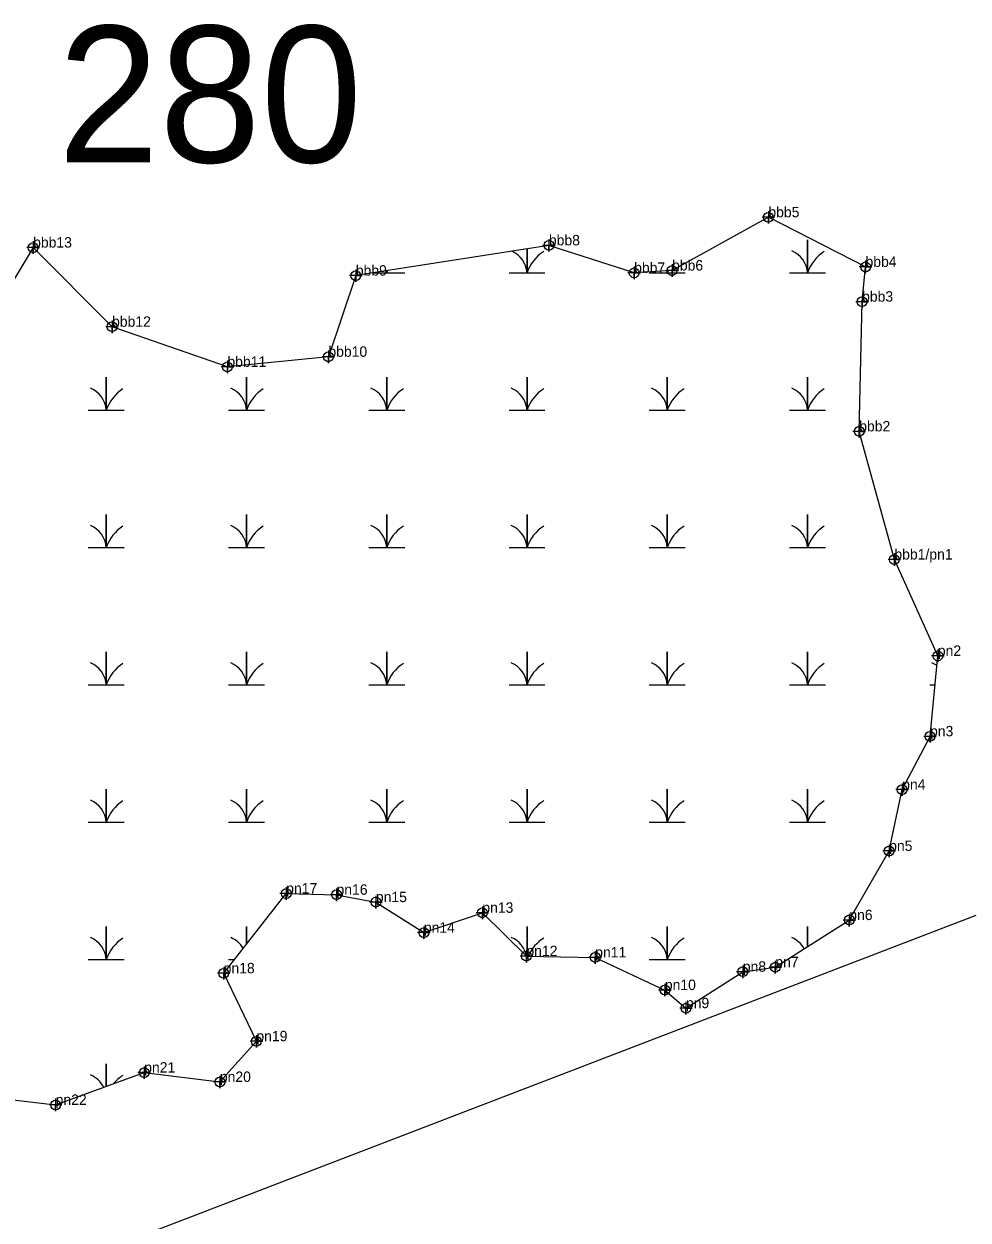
# Model space of a CAD drawing. Extents: x 2071991 to 2268989, y 436479 to 469629.
# Drawn here: x 2242081 to 2242534, y 439959 to 440532 of the extents above; entities that cross this region are included whole.
import ezdxf

# ---------------------------------------------------------------- set-up
doc = ezdxf.new("R2010")
doc.units = 0
for name, color, linetype in [('approx_PSA', 7, 'Continuous'), ('Default', 7, 'Continuous'), ('Exist Environmental Wetland Boundary', 7, 'Continuous'), ('Exist Environmental Wetland Boundary Cogo Comment', 7, 'Continuous'), ('Exist Environmental Wetland Boundary Cogo Point CELL', 7, 'Continuous'), ('Exist Hydro Swamp or Marsh', 7, 'Continuous')]:
    doc.layers.add(name, color=color, linetype=linetype)

msp = doc.modelspace()

# ---------------------------------------------------------------- linework, layer by layer
at = {"layer": 'approx_PSA'}
msp.add_line((2242537.57, 440104.72), (2241491, 439703.18), dxfattribs=at)
at = {"layer": 'Exist Environmental Wetland Boundary'}
msp.add_lwpolyline([(2242062.43, 440018.03), (2242096.69, 440014.03), (2242139.12, 440029.51), (2242175.36, 440025.04), (2242192.89, 440044.51), (2242177.2, 440077.07), (2242207.17, 440115.29), (2242231.28, 440114.71), (2242250.14, 440111.17), (2242273.12, 440096.55), (2242301.15, 440106.06), (2242322.27, 440085.32), (2242355.23, 440084.68), (2242388.6, 440069.06), (2242398.71, 440060.37), (2242425.95, 440077.83), (2242441.53, 440080.02), (2242476.97, 440102.58), (2242496.07, 440135.68), (2242502.31, 440165.05), (2242515.66, 440190.59), (2242519.41, 440229.14), (2242498.59, 440275.3), (2242481.72, 440336.67), (2242483.1, 440398.81), (2242484.75, 440415.48), (2242438.2, 440439.24), (2242392.06, 440413.73), (2242373.89, 440412.62), (2242333.04, 440425.78), (2242240.52, 440411.29), (2242227.38, 440372.41), (2242179, 440367.6), (2242123.71, 440386.79), (2242085.9, 440424.73), (2242061.66, 440384.54)], dxfattribs=at)
at = {"layer": 'Exist Environmental Wetland Boundary Cogo Point CELL'}
for points in [[(2242438.2, 440442.24), (2242438.2, 440436.24), (2242438.2, 440439.24), (2242441.2, 440439.24), (2242435.2, 440439.24)], [(2242333.04, 440428.78), (2242333.04, 440422.78), (2242333.04, 440425.78), (2242336.04, 440425.78), (2242330.04, 440425.78)], [(2242085.9, 440427.73), (2242085.9, 440421.73), (2242085.9, 440424.73), (2242088.9, 440424.73), (2242082.9, 440424.73)], [(2242392.06, 440416.73), (2242392.06, 440410.73), (2242392.06, 440413.73), (2242395.06, 440413.73), (2242389.06, 440413.73)], [(2242484.75, 440418.48), (2242484.75, 440412.48), (2242484.75, 440415.48), (2242487.75, 440415.48), (2242481.75, 440415.48)], [(2242240.52, 440414.29), (2242240.52, 440408.29), (2242240.52, 440411.29), (2242243.52, 440411.29), (2242237.52, 440411.29)], [(2242373.89, 440415.62), (2242373.89, 440409.62), (2242373.89, 440412.62), (2242376.89, 440412.62), (2242370.89, 440412.62)], [(2242483.1, 440401.81), (2242483.1, 440395.81), (2242483.1, 440398.81), (2242486.1, 440398.81), (2242480.1, 440398.81)], [(2242123.71, 440389.79), (2242123.71, 440383.79), (2242123.71, 440386.79), (2242126.71, 440386.79), (2242120.71, 440386.79)], [(2242179, 440370.6), (2242179, 440364.6), (2242179, 440367.6), (2242182, 440367.6), (2242176, 440367.6)], [(2242227.38, 440375.41), (2242227.38, 440369.41), (2242227.38, 440372.41), (2242230.38, 440372.41), (2242224.38, 440372.41)], [(2242481.72, 440339.67), (2242481.72, 440333.67), (2242481.72, 440336.67), (2242484.72, 440336.67), (2242478.72, 440336.67)], [(2242498.59, 440278.3), (2242498.59, 440272.3), (2242498.59, 440275.3), (2242501.59, 440275.3), (2242495.59, 440275.3)], [(2242519.41, 440232.14), (2242519.41, 440226.14), (2242519.41, 440229.14), (2242522.41, 440229.14), (2242516.41, 440229.14)], [(2242515.66, 440193.59), (2242515.66, 440187.59), (2242515.66, 440190.59), (2242518.66, 440190.59), (2242512.66, 440190.59)], [(2242502.31, 440168.05), (2242502.31, 440162.05), (2242502.31, 440165.05), (2242505.31, 440165.05), (2242499.31, 440165.05)], [(2242496.07, 440138.68), (2242496.07, 440132.68), (2242496.07, 440135.68), (2242499.07, 440135.68), (2242493.07, 440135.68)], [(2242207.17, 440118.29), (2242207.17, 440112.29), (2242207.17, 440115.29), (2242210.17, 440115.29), (2242204.17, 440115.29)], [(2242231.28, 440117.71), (2242231.28, 440111.71), (2242231.28, 440114.71), (2242234.28, 440114.71), (2242228.28, 440114.71)], [(2242250.14, 440114.17), (2242250.14, 440108.17), (2242250.14, 440111.17), (2242253.14, 440111.17), (2242247.14, 440111.17)], [(2242301.15, 440109.06), (2242301.15, 440103.06), (2242301.15, 440106.06), (2242304.15, 440106.06), (2242298.15, 440106.06)], [(2242476.97, 440105.58), (2242476.97, 440099.58), (2242476.97, 440102.58), (2242479.97, 440102.58), (2242473.97, 440102.58)], [(2242273.12, 440099.55), (2242273.12, 440093.55), (2242273.12, 440096.55), (2242276.12, 440096.55), (2242270.12, 440096.55)], [(2242322.27, 440088.32), (2242322.27, 440082.32), (2242322.27, 440085.32), (2242325.27, 440085.32), (2242319.27, 440085.32)], [(2242355.23, 440087.68), (2242355.23, 440081.68), (2242355.23, 440084.68), (2242358.23, 440084.68), (2242352.23, 440084.68)], [(2242177.2, 440080.07), (2242177.2, 440074.07), (2242177.2, 440077.07), (2242180.2, 440077.07), (2242174.2, 440077.07)], [(2242425.95, 440080.83), (2242425.95, 440074.83), (2242425.95, 440077.83), (2242428.95, 440077.83), (2242422.95, 440077.83)], [(2242441.53, 440083.02), (2242441.53, 440077.02), (2242441.53, 440080.02), (2242444.53, 440080.02), (2242438.53, 440080.02)], [(2242388.6, 440072.06), (2242388.6, 440066.06), (2242388.6, 440069.06), (2242391.6, 440069.06), (2242385.6, 440069.06)], [(2242398.71, 440063.37), (2242398.71, 440057.37), (2242398.71, 440060.37), (2242401.71, 440060.37), (2242395.71, 440060.37)], [(2242192.89, 440047.51), (2242192.89, 440041.51), (2242192.89, 440044.51), (2242195.89, 440044.51), (2242189.89, 440044.51)], [(2242139.12, 440032.51), (2242139.12, 440026.51), (2242139.12, 440029.51), (2242142.12, 440029.51), (2242136.12, 440029.51)], [(2242175.36, 440028.04), (2242175.36, 440022.04), (2242175.36, 440025.04), (2242178.36, 440025.04), (2242172.36, 440025.04)], [(2242096.69, 440017.03), (2242096.69, 440011.03), (2242096.69, 440014.03), (2242099.69, 440014.03), (2242093.69, 440014.03)]]:
    msp.add_lwpolyline(points, dxfattribs=at)
for centre in [(2242438.2, 440439.24), (2242333.04, 440425.78), (2242085.9, 440424.73), (2242484.75, 440415.48), (2242240.52, 440411.29), (2242373.89, 440412.62), (2242392.06, 440413.73), (2242483.1, 440398.81), (2242123.71, 440386.79), (2242227.38, 440372.41), (2242179, 440367.6), (2242481.72, 440336.67), (2242498.59, 440275.3), (2242519.41, 440229.14), (2242515.66, 440190.59), (2242502.31, 440165.05), (2242496.07, 440135.68), (2242207.17, 440115.29), (2242231.28, 440114.71), (2242250.14, 440111.17), (2242301.15, 440106.06), (2242476.97, 440102.58), (2242273.12, 440096.55), (2242322.27, 440085.32), (2242355.23, 440084.68), (2242177.2, 440077.07), (2242425.95, 440077.83), (2242441.53, 440080.02), (2242388.6, 440069.06), (2242398.71, 440060.37), (2242192.89, 440044.51), (2242139.12, 440029.51), (2242175.36, 440025.04), (2242096.69, 440014.03)]:
    msp.add_circle(centre, 2.34, dxfattribs=at)
at = {"layer": 'Exist Hydro Swamp or Marsh'}
for p, q in [((2242515.56, 440215.3), (2242518.06, 440215.3)), ((2242179.54, 440083.74), (2242182.43, 440083.74))]:
    msp.add_line(p, q, dxfattribs=at)
for points in [[(2242448.35, 440412.64), (2242456.96, 440412.64), (2242456.96, 440428.42), (2242456.96, 440412.64), (2242465.56, 440412.64)], [(2242313.95, 440412.64), (2242322.55, 440412.64), (2242322.55, 440424.13)], [(2242322.55, 440424.13), (2242322.55, 440412.64), (2242331.15, 440412.64)], [(2242249.11, 440412.64), (2242255.35, 440412.64), (2242255.35, 440413.61)], [(2242255.35, 440413.61), (2242255.35, 440412.64), (2242263.95, 440412.64)], [(2242381.15, 440412.64), (2242389.75, 440412.64), (2242389.75, 440413.58)], [(2242389.75, 440413.58), (2242389.75, 440412.64), (2242398.35, 440412.64)], [(2242112.34, 440346.86), (2242120.94, 440346.86), (2242120.94, 440362.64), (2242120.94, 440346.86), (2242129.54, 440346.86)], [(2242179.54, 440346.86), (2242188.14, 440346.86), (2242188.14, 440362.64), (2242188.14, 440346.86), (2242196.74, 440346.86)], [(2242246.74, 440346.86), (2242255.35, 440346.86), (2242255.35, 440362.64), (2242255.35, 440346.86), (2242263.95, 440346.86)], [(2242313.95, 440346.86), (2242322.55, 440346.86), (2242322.55, 440362.64), (2242322.55, 440346.86), (2242331.15, 440346.86)], [(2242381.15, 440346.86), (2242389.75, 440346.86), (2242389.75, 440362.64), (2242389.75, 440346.86), (2242398.35, 440346.86)], [(2242448.35, 440346.86), (2242456.96, 440346.86), (2242456.96, 440362.64), (2242456.96, 440346.86), (2242465.56, 440346.86)], [(2242112.34, 440281.08), (2242120.94, 440281.08), (2242120.94, 440296.86), (2242120.94, 440281.08), (2242129.54, 440281.08)], [(2242179.54, 440281.08), (2242188.14, 440281.08), (2242188.14, 440296.86), (2242188.14, 440281.08), (2242196.74, 440281.08)], [(2242246.74, 440281.08), (2242255.35, 440281.08), (2242255.35, 440296.86), (2242255.35, 440281.08), (2242263.95, 440281.08)], [(2242313.95, 440281.08), (2242322.55, 440281.08), (2242322.55, 440296.86), (2242322.55, 440281.08), (2242331.15, 440281.08)], [(2242381.15, 440281.08), (2242389.75, 440281.08), (2242389.75, 440296.86), (2242389.75, 440281.08), (2242398.35, 440281.08)], [(2242448.35, 440281.08), (2242456.96, 440281.08), (2242456.96, 440296.86), (2242456.96, 440281.08), (2242465.56, 440281.08)], [(2242112.34, 440215.3), (2242120.94, 440215.3), (2242120.94, 440231.08), (2242120.94, 440215.3), (2242129.54, 440215.3)], [(2242179.54, 440215.3), (2242188.14, 440215.3), (2242188.14, 440231.08), (2242188.14, 440215.3), (2242196.74, 440215.3)], [(2242246.74, 440215.3), (2242255.35, 440215.3), (2242255.35, 440231.08), (2242255.35, 440215.3), (2242263.95, 440215.3)], [(2242313.95, 440215.3), (2242322.55, 440215.3), (2242322.55, 440231.08), (2242322.55, 440215.3), (2242331.15, 440215.3)], [(2242381.15, 440215.3), (2242389.75, 440215.3), (2242389.75, 440231.08), (2242389.75, 440215.3), (2242398.35, 440215.3)], [(2242448.35, 440215.3), (2242456.96, 440215.3), (2242456.96, 440231.08), (2242456.96, 440215.3), (2242465.56, 440215.3)], [(2242112.34, 440149.52), (2242120.94, 440149.52), (2242120.94, 440165.3), (2242120.94, 440149.52), (2242129.54, 440149.52)], [(2242179.54, 440149.52), (2242188.14, 440149.52), (2242188.14, 440165.3), (2242188.14, 440149.52), (2242196.74, 440149.52)], [(2242246.74, 440149.52), (2242255.35, 440149.52), (2242255.35, 440165.3), (2242255.35, 440149.52), (2242263.95, 440149.52)], [(2242313.95, 440149.52), (2242322.55, 440149.52), (2242322.55, 440165.3), (2242322.55, 440149.52), (2242331.15, 440149.52)], [(2242381.15, 440149.52), (2242389.75, 440149.52), (2242389.75, 440165.3), (2242389.75, 440149.52), (2242398.35, 440149.52)], [(2242448.35, 440149.52), (2242456.96, 440149.52), (2242456.96, 440165.3), (2242456.96, 440149.52), (2242465.56, 440149.52)], [(2242112.34, 440083.74), (2242120.94, 440083.74), (2242120.94, 440099.52), (2242120.94, 440083.74), (2242129.54, 440083.74)], [(2242188.14, 440091.03), (2242188.14, 440099.52), (2242188.14, 440091.03)], [(2242322.55, 440085.32), (2242322.55, 440099.52), (2242322.55, 440085.32)], [(2242381.15, 440083.74), (2242389.75, 440083.74), (2242389.75, 440099.52), (2242389.75, 440083.74), (2242398.35, 440083.74)], [(2242456.96, 440089.84), (2242456.96, 440099.52), (2242456.96, 440089.84)], [(2242120.94, 440022.88), (2242120.94, 440033.74), (2242120.94, 440022.88)]]:
    msp.add_lwpolyline(points, dxfattribs=at)
for centre, radius, start, end in [((2242310.28, 440411.75), 12.3, 4.14034, 66.09955), ((2242340.79, 440406.58), 19.22, 122.12745, 161.62219), ((2242444.69, 440411.75), 12.3, 4.14034, 67.53497), ((2242475.2, 440406.58), 19.22, 122.12745, 161.62219), ((2242243.08, 440411.75), 12.3, 4.14034, 8.63769), ((2242273.59, 440406.58), 19.22, 158.33855, 161.62219), ((2242377.49, 440411.75), 12.3, 4.14034, 8.54677), ((2242408, 440406.58), 19.22, 158.5546, 161.62219), ((2242108.67, 440345.97), 12.3, 4.14034, 67.53497), ((2242139.18, 440340.8), 19.22, 122.12745, 161.62219), ((2242175.88, 440345.97), 12.3, 4.14034, 67.53497), ((2242206.39, 440340.8), 19.22, 122.12745, 161.62219), ((2242243.08, 440345.97), 12.3, 4.14034, 67.53497), ((2242273.59, 440340.8), 19.22, 122.12745, 161.62219), ((2242310.28, 440345.97), 12.3, 4.14034, 67.53497), ((2242340.79, 440340.8), 19.22, 122.12745, 161.62219), ((2242377.49, 440345.97), 12.3, 4.14034, 67.53497), ((2242408, 440340.8), 19.22, 122.12745, 161.62219), ((2242444.69, 440345.97), 12.3, 4.14034, 67.53497), ((2242475.2, 440340.8), 19.22, 122.12745, 161.62219), ((2242108.67, 440280.19), 12.3, 4.14034, 67.53497), ((2242139.18, 440275.02), 19.22, 122.12745, 161.62219), ((2242175.88, 440280.19), 12.3, 4.14034, 67.53497), ((2242206.39, 440275.02), 19.22, 122.12745, 161.62219), ((2242243.08, 440280.19), 12.3, 4.14034, 67.53497), ((2242273.59, 440275.02), 19.22, 122.12745, 161.62219), ((2242310.28, 440280.19), 12.3, 4.14034, 67.53497), ((2242340.79, 440275.02), 19.22, 122.12745, 161.62219), ((2242377.49, 440280.19), 12.3, 4.14034, 67.53497), ((2242408, 440275.02), 19.22, 122.12745, 161.62219), ((2242444.69, 440280.19), 12.3, 4.14034, 67.53497), ((2242475.2, 440275.02), 19.22, 122.12745, 161.62219), ((2242108.67, 440214.41), 12.3, 4.14034, 67.53497), ((2242139.18, 440209.24), 19.22, 122.12745, 161.62219), ((2242175.88, 440214.41), 12.3, 4.14034, 67.53497), ((2242206.39, 440209.24), 19.22, 122.12745, 161.62219), ((2242243.08, 440214.41), 12.3, 4.14034, 67.53497), ((2242273.59, 440209.24), 19.22, 122.12745, 161.62219), ((2242310.28, 440214.41), 12.3, 4.14034, 67.53497), ((2242340.79, 440209.24), 19.22, 122.12745, 161.62219), ((2242377.49, 440214.41), 12.3, 4.14034, 67.53497), ((2242408, 440209.24), 19.22, 122.12745, 161.62219), ((2242444.69, 440214.41), 12.3, 4.14034, 67.53497), ((2242475.2, 440209.24), 19.22, 122.12745, 161.62219), ((2242511.89, 440214.41), 12.3, 54.9669, 67.53497), ((2242108.67, 440148.63), 12.3, 4.14034, 67.53497), ((2242139.18, 440143.46), 19.22, 122.12745, 161.62219), ((2242175.88, 440148.63), 12.3, 4.14034, 67.53497), ((2242206.39, 440143.46), 19.22, 122.12745, 161.62219), ((2242243.08, 440148.63), 12.3, 4.14034, 67.53497), ((2242273.59, 440143.46), 19.22, 122.12745, 161.62219), ((2242310.28, 440148.63), 12.3, 4.14034, 67.53497), ((2242340.79, 440143.46), 19.22, 122.12745, 161.62219), ((2242377.49, 440148.63), 12.3, 4.14034, 67.53497), ((2242408, 440143.46), 19.22, 122.12745, 161.62219), ((2242444.69, 440148.63), 12.3, 4.14034, 67.53497), ((2242475.2, 440143.46), 19.22, 122.12745, 161.62219), ((2242108.67, 440082.85), 12.3, 4.14034, 67.53497), ((2242139.18, 440077.68), 19.22, 122.12745, 161.62219), ((2242175.88, 440082.85), 12.3, 29.90293, 67.53497), ((2242310.28, 440082.85), 12.3, 11.59612, 67.53497), ((2242340.79, 440077.68), 19.22, 122.12745, 156.61729), ((2242377.49, 440082.85), 12.3, 4.14034, 67.53497), ((2242408, 440077.68), 19.22, 122.12745, 161.62219), ((2242444.69, 440082.85), 12.3, 29.25588, 67.53497), ((2242108.67, 440017.07), 12.3, 25.90138, 67.53497), ((2242139.18, 440011.89), 19.22, 122.12745, 140.49752)]:
    msp.add_arc(centre, radius, start, end, dxfattribs=at)

# ---------------------------------------------------------------- texts
at = {"layer": 'Default'}
msp.add_text('280', height=65.34, dxfattribs=at).set_placement((2242097.76, 440465.55))
at = {"layer": 'Exist Environmental Wetland Boundary Cogo Comment'}
for s, p in [('bbb5', (2242438.2, 440439.24)), ('bbb13', (2242085.9, 440424.73)), ('bbb8', (2242333.04, 440425.78)), ('bbb9', (2242240.52, 440411.29)), ('bbb7', (2242373.89, 440412.62)), ('bbb6', (2242392.06, 440413.73)), ('bbb4', (2242484.75, 440415.48)), ('bbb3', (2242483.1, 440398.81)), ('bbb12', (2242123.71, 440386.79)), ('bbb10', (2242227.38, 440372.41)), ('bbb11', (2242179, 440367.6)), ('bbb2', (2242481.72, 440336.67)), ('bbb1/pn1', (2242498.59, 440275.3)), ('pn2', (2242519.41, 440229.14)), ('pn3', (2242515.66, 440190.59)), ('pn4', (2242502.31, 440165.05)), ('pn5', (2242496.07, 440135.68)), ('pn17', (2242207.17, 440115.29)), ('pn16', (2242231.28, 440114.71)), ('pn15', (2242250.14, 440111.17)), ('pn13', (2242301.15, 440106.06)), ('pn6', (2242476.97, 440102.58)), ('pn14', (2242273.12, 440096.55)), ('pn12', (2242322.27, 440085.32)), ('pn11', (2242355.23, 440084.68)), ('pn7', (2242441.53, 440080.02)), ('pn18', (2242177.2, 440077.07)), ('pn8', (2242425.95, 440077.83)), ('pn10', (2242388.6, 440069.06)), ('pn9', (2242398.71, 440060.37)), ('pn19', (2242192.89, 440044.51)), ('pn21', (2242139.12, 440029.51)), ('pn20', (2242175.36, 440025.04)), ('pn22', (2242096.69, 440014.03))]:
    msp.add_text(s, height=5, dxfattribs=at).set_placement(p)

doc.saveas('drawing.dxf')
